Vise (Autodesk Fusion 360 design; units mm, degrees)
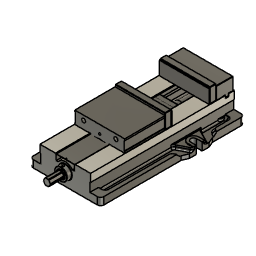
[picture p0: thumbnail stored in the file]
description: HaasClamp
base_feature "Base Feature1"
base_feature "Base Feature1"
base_feature "Base Feature1"
base_feature "Base Feature1"
base_feature "Base Feature1"
base_feature "Base Feature1"
base_feature "Base Feature1"
base_feature "Base Feature1"
base_feature "Base Feature1"
base_feature "Base Feature1"
as_built_joint "As-built1"
as_built_joint "As-built2"
as_built_joint "As-built3"
joint_origin "JointOrigin1" OffsetX 0 OffsetY 0 OffsetZ 0 AngleZ 0
joint "Assemble1" alignAngle 180 alignOffsetX 0 alignOffsetY 0 alignOffsetZ 0 (= "jaw_width_haas_050002") SlideMaximum 22.5 SlideMinimum 0
position "Position1"
sketch "Sketch1" plane through (0, -72.5, 0) normal (0, -1, 0) x axis (1, 0, 0)
  line L1 (75, 73) -> (-75, 73)
  line L2 (76, 74) -> (75, 73)
  line L3 (76, 116.5) -> (76, 74)
  line L4 (75, 117.5) -> (76, 116.5)
  line L5 (-75, 117.5) -> (75, 117.5)
  line L6 (-76, 116.5) -> (-75, 117.5)
  line L7 (-76, 74) -> (-76, 116.5)
  line L8 (-75, 73) -> (-76, 74)
  line L9 (76.4, 114.275) -> (-76, 114.275)
  line L10 (76.4, 73) -> (76.4, 114.275)
  line L11 (-76, 73) -> (76.4, 73)
  line L12 (-76, 114.275) -> (-76, 73)
  circle C1 centre (49.21, 96.8) radius 11
  circle C2 centre (-49.21, 96.8) radius 11
  point P14 (76.4, 73)
  point P12 (-76, 114.275)
  point P13 (76.4, 114.275)
  horizontal L9
  vertical L10
  horizontal L11
  vertical L12
  coincident L1 P14
  coincident L7 P12
  dimension "d16" distance P12 P13 = 152.4
  dimension "d17" distance P13 P14 = 41.275
place_component sketch "Sketch1"
extrude "Extrude1" new body sketch "Sketch1" profile of L1 L2 L3 L7 L8 C1 C2 L9 L11 L12 along normal blind 3.175
place_component sketch "Sketch1"
extrude "Extrude1" sketch "Sketch1" profile of L1 L2 L3 L7 L8 C1 C2 L9 L11 L12 blind -3.175
as_built_joint "As-built5"
as_built_joint "As-built6"
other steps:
create_component "CreateComponent1"
create_component "CreateComponent2"
create_component "CreateComponent3"
create_component "CreateComponent4"
create_component "CreateComponent5"
create_component "CreateComponent6"
create_component "CreateComponent7"
create_component "CreateComponent8"
create_component "CreateComponent9"
create_component "CreateComponent10"
joint_origin "JointOrigin10"
joint_origin "JointOrigin11"
create_component "CreateComponent11" sketch "Sketch1"
create_component "CreateComponent12" sketch "Sketch1"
